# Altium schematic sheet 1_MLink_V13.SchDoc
size 292 x 220 mm; PageSetup: Record=PageOptions|CenterHorizontal=True|CenterVertical=True|PrintScale=0.94|XCorrection=1.00|YCorrection=1.00|PrintKind=0|BorderSize=5000000|LeftOffset=0|BottomOffset=0|Orientation=2|PaperLength=1000|PaperWidth=1000|Scale=100|PaperSource=7|PrintQuality=-4|MediaType=1|DitherType=10|PaperKind=A4 (210 x 297 mm)|PrintScaleMode=1
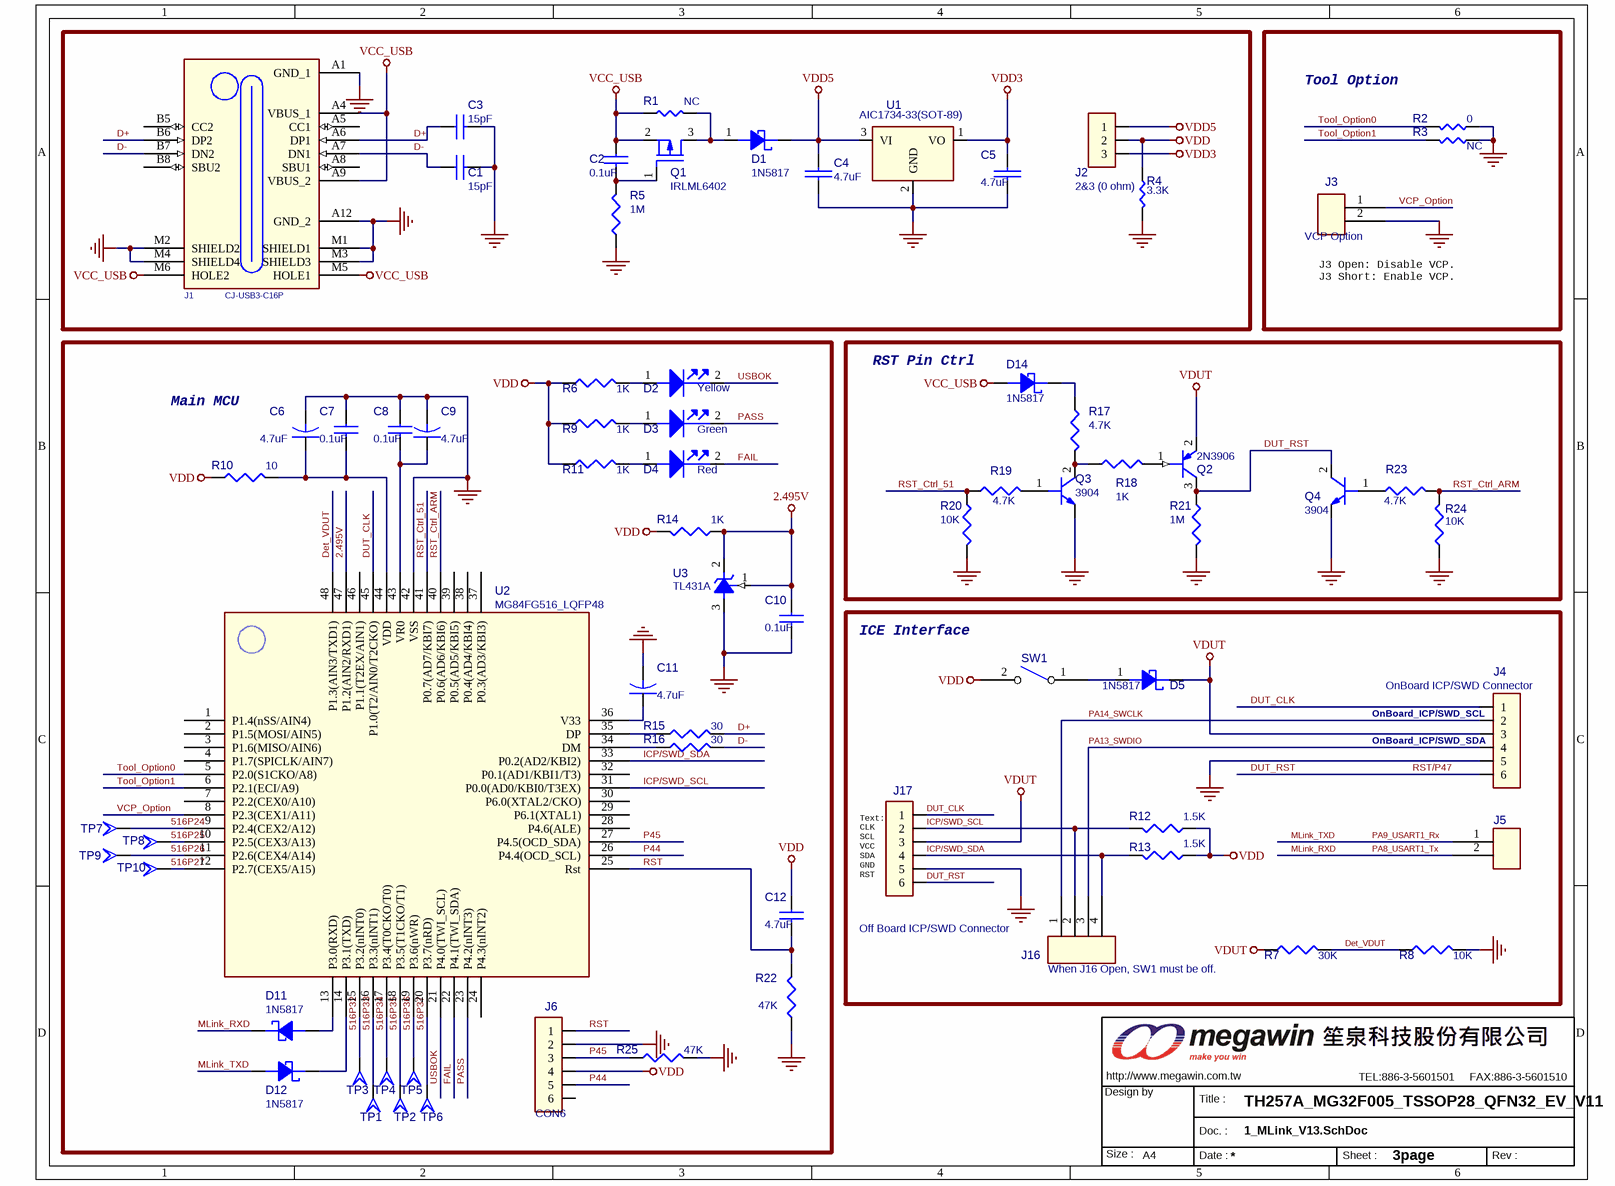
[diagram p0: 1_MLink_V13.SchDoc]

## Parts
C1  15pF  [0603C]
C2  0.1uF  [0603C]
C3  15pF  [0603C]
C4  4.7uF  [0805C]
C5  4.7uF  [0805C]
C6  4.7uF  [0805C]
C7  0.1uF  [0603C]
C8  0.1uF  [0603C]
C9  4.7uF  [0805C]
C10  0.1uF  [0603C]
C11  4.7uF  [0805C]
C12  4.7uF  [0805C]
D1  1N5817  [DIODE_SMA_SOD323]
D2  Yellow  [0805D]
D3  Green  [0805D]
D4  Red  [0805D]
D5  1N5817  [DIODE_SMA_SOD323]
D11  1N5817  [DIODE_SMA_SOD323]
D12  1N5817  [DIODE_SMA_SOD323]
D14  1N5817  [DIODE_SMA_SOD323]
J1  CJ-USB3-C16P  [USB_CF_16_SMD]
J2  2&3 (0 ohm)  [PS3P254]
J3  VCP Option  [PS2P254]
J4  OnBoard ICP/SWD Connector  [PS6P254]
J5  NC  [PS2P254]  (value not drawn)
J6  CON6  [PS6P254]
J16  When J16 Open, SW1 must be off.  [PS4P254]
J17  Off Board ICP/SWD Connector  [PS6P254_90]
MW1  OrgAddr3: TEL:886-3-5601501     FAX:886-3-5601510  [MEGAWIN_3.4_1]  (hidden comment: MW-A4)  (no BOM)
Q1  IRLML6402  [SOT23]
Q2  2N3906  [SOT23]
Q3  3904  [SOT23_132]
Q4  3904  [SOT23_132]
R1  NC  [0603R]
R2  0  [0603R]
R3  NC  [0603R]
R4  3.3K  [0603R]
R5  1M  [0603R]
R6  1K  [0603R]
R7  30K  [0603R]
R8  10K  [0603R]
R9  1K  [0603R]
R10  10  [0603R]
R11  1K  [0603R]
R12  1.5K  [0603R]
R13  1.5K  [0603R]
R14  1K  [0603R]
R15  30  [0603R]
R16  30  [0603R]
R17  4.7K  [0603R]
R18  1K  [0603R]
R19  4.7K  [0603R]
R20  10K  [0603R]
R21  1M  [0603R]
R22  47K  [0603R]
R23  4.7K  [0603R]
R24  10K  [0603R]
R25  47K  [0603R]
SW1  SW KEY-SPST  [DIP2_SW]  (value not drawn)
TP1  T POINT A  [PIN1_1H0]  (value not drawn)
TP2  T POINT A  [PIN1_1H0]  (value not drawn)
TP3  T POINT A  [PIN1_1H0]  (value not drawn)
TP4  T POINT A  [PIN1_1H0]  (value not drawn)
TP5  T POINT A  [PIN1_1H0]  (value not drawn)
TP6  T POINT A  [PIN1_1H0]  (value not drawn)
TP7  T POINT A  [PIN1_1H0]  (value not drawn)
TP8  T POINT A  [PIN1_1H0]  (value not drawn)
TP9  T POINT A  [PIN1_1H0]  (value not drawn)
TP10  T POINT A  [PIN1_1H0]  (value not drawn)
U1  AIC1734-33(SOT-89)  [SOT89]
U2  MG84FG516_LQFP48  [LQFP48_7X7_050]
U3  TL431A  [SOT23]

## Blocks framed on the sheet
Tool Option: J3 R2 R3
Main MCU: C6-C12 D2-D4 D11 D12 J6 R6 R9-R11 R14-R16 R22 R25 TP1-TP10 U2 U3
RST Pin Ctrl: D14 Q2-Q4 R17-R21 R23 R24
ICE Interface: D5 J4 J5 J16 J17 R7 R8 R12 R13 SW1

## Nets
2.495V: C10.1 R14.1 U2.47(P1.2(AIN2/RXD1)) U3.1(VREF) U3.2(C)
GND_POWER: C1.2 C3.2 C4.2 C5.2 C6.2 C7.1 C8.1 C9.2 C10.2 C11.2 J1.A1(GND_1) J1.A12(GND_2) J1.M1(SHIELD1) J1.M2(SHIELD2) J1.M3(SHIELD3) J1.M4(SHIELD4) J3.2 J4.5 J6.2 J17.5 Q3.3(E) Q4.3(E) R2.2 R3.2 R4.2 R5.1 R8.2 R20.2 R21.2 R22.1 R24.2 R25.2 U1.2(GND) U2.42(VSS) U3.3(A)
VCC_USB: C2.1 D14.1(ANODE) J1.A4(VBUS_1) J1.A9(VBUS_2) J1.M5(HOLE1) J1.M6(HOLE2) Q1.2(S) R1.1
VDD: C12.1 J2.2 J6.4 R4.1 R6.1 R9.1 R10.1 R11.1 R12.1 R13.1 R14.2 SW1.2
VDD3: C5.1 J2.3 U1.1(VO)
VDD5: C4.1 D1.2(CATHODE) J2.1 U1.3(VI)
VDUT: D5.2(CATHODE) J4.3 J17.3 Q2.2(EMITTER) R7.1
516P24: TP7.1(TP) U2.9(P2.4(CEX2/A12))
516P25: TP8.1(TP) U2.10(P2.5(CEX3/A13))
516P26: TP9.1(TP) U2.11(P2.6(CEX4/A14))
516P27: TP10.1(TP) U2.12(P2.7(CEX5/A15))
516P32: TP3.1(TP) U2.15(P3.2(nINT0))
516P33: TP1.1(TP) U2.16(P3.3(nINT1))
516P34: TP4.1(TP) U2.17(P3.4(T0CKO/T0))
516P35: TP2.1(TP) U2.18(P3.5(T1CKO/T1))
516P36: TP5.1(TP) U2.19(P3.6(nWR))
516P37: TP6.1(TP) U2.20(P3.7(nRD))
D+: C3.1 J1.A6(DP1) J1.B6(DP2) R15.2
D-: C1.1 J1.A7(DN1) J1.B7(DN2) R16.2
Det_VDUT: R7.2 R8.1 U2.48(P1.3(AIN3/TXD1))
DUT_CLK: J4.1 J17.1 U2.45(P1.0(T2/AIN0/T2CKO))
DUT_RST: J4.6 J17.6 Q2.3(COLLECTOR) Q4.2(C) R21.1  [also labelled RST/P47]
FAIL: D4.2 U2.22(P4.1(TWI_SDA))
ICP/SWD_SCL: J16.2 J17.2 R12.2 U2.31(P0.0(AD0/KBI0/T3EX))
ICP/SWD_SDA: J16.4 J17.4 R13.2 U2.33(P0.2(AD2/KBI2))
MLink_RXD: D11.2(CATHODE) J5.2  [also labelled PA8_USART1_Tx]
MLink_TXD: D12.1(ANODE) J5.1  [also labelled PA9_USART1_Rx]
P44: J6.5 U2.26(P4.4(OCD_SCL))
P45: J6.3 R25.1 U2.27(P4.5(OCD_SDA))
PA13_SWDIO: J4.4 J16.3
PA14_SWCLK: J4.2 J16.1
PASS: D3.2 U2.23(P4.2(nINT3))
RST: C12.2 J6.1 R22.2 U2.25(Rst)
RST_Ctrl_51: R19.1 R20.1 U2.41(P0.7(AD7/KBI7))
RST_Ctrl_ARM: R23.1 R24.1 U2.40(P0.6(AD6/KBI6))
Tool_Option0: R2.1 U2.5(P2.0(S1CKO/A8))
Tool_Option1: R3.1 U2.6(P2.1(ECI/A9))
USBOK: D2.2 U2.21(P4.0(TWI_SCL))
VCP_Option: J3.1 U2.8(P2.3(CEX1/A11))
NetC2_2: C2.2 Q1.1(G) R5.2
NetC6_1: C6.1 C7.2 R10.2 U2.44(VDD)
NetC8_2: C8.2 C9.1 U2.43(VR0)
NetC11_1: C11.1 U2.36(V33)
NetD1_1: D1.1(ANODE) Q1.3(D) R1.2
NetD2_1: D2.1 R6.2
NetD3_1: D3.1 R9.2
NetD4_1: D4.1 R11.2
NetD5_1: D5.1(ANODE) SW1.1
NetD11_1: D11.1(ANODE) U2.13(P3.0(RXD))
NetD12_2: D12.2(CATHODE) U2.14(P3.1(TXD))
NetD14_2: D14.2(CATHODE) R17.1
NetQ2_1: Q2.1(BASE) R18.2
NetQ3_1: Q3.1(B) R19.2
NetQ3_2: Q3.2(C) R17.2 R18.1
NetQ4_1: Q4.1(B) R23.2
NetR15_1: R15.1 U2.35(DP)
NetR16_1: R16.1 U2.34(DM)

Not connected (* = marked no-connect by the designer): J1 A5(CC1) A8(SBU1) B5(CC2) B8(SBU2); J6 6; U2 1(P1.4(nSS/AIN4)) 2(P1.5(MOSI/AIN5)) 3(P1.6(MISO/AIN6)) 4(P1.7(SPICLK/AIN7)) 7(P2.2(CEX0/A10)) 24(P4.3(nINT2)) 28(P4.6(ALE)) 29(P6.1(XTAL1)) 30(P6.0(XTAL2/CKO)) 32(P0.1(AD1/KBI1/T3)) 37(P0.3(AD3/KBI3)) 38(P0.4(AD4/KBI4)) 39(P0.5(AD5/KBI5)) 46(P1.1(T2EX/AIN1))

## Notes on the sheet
- (near J3) J3 Open: Disable VCP.
  J3 Short: Enable VCP.
- (near J4) OnBoard_ICP/SWD_SCL
- (near J4) OnBoard_ICP/SWD_SDA
- (near J17) Text:
  CLK
  SCL
  VCC
  SDA
  GND
  RST
- TH257A_MG32F005_TSSOP28_QFN32_EV_V11
- 3page

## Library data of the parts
C1 C3 C7 C12 = CAP NP_Dup1
C2 C8 C10 = CAP NP
C4 C5 = C NP
C6 C9 C11 = CAP
D1 D5 D11 D12 D14 = DIODE SCHOTTKY
D2-D4 = Led0_0
J1 = CJ-USB3-C16P: TPYE-C-9; Name: Type-c
J2 = CON3
J3 J5 = CON2
J4 J17 = CON6
J16 = CON4
MW1 = MW_A4_2
Q1 = MOSFET P GSD
Q2 = 2N3906_0
Q3 Q4 = NPN BCE
R1-R4 = R_Dup4
R5-R9 R11-R13 R17-R19 R22 R23 R25 = R_Dup2
R10 R14-R16 = R_Dup5
R20 R21 R24 = R_Dup1
U1 = AIC1722-33
U3 = TL431/CYL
